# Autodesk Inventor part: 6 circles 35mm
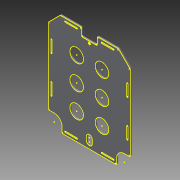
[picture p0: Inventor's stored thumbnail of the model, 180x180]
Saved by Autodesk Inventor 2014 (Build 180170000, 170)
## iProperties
Created: 2014-05
Part Number: 6 circles 35mm
Material: Generic
Document SubType Name: Modeling
Designer: Designer
Density: 1 g/cm^3
Appearance: Default
Author: Designer
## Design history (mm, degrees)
sketch "Sketch1" dims "d120" = 10, "d132" = 10
  geometry: L1 (97.5, 0)-(97.5, 10); L2 (82.5, 10)-(82.5, 0); L3 (17, 40)-(25, 40); L4 (25, 20)-(17, 20); L5 (15, 22)-(15, 38); L6 (195, 214.172)-(195, 22); L7 (158, -15)-(22, -15); L8 (-15, 22)-(-15, 214.172); L9 (-13, 20)-(0, 20); L10 (20, 0)-(20, -13); L11 (160, -13)-(160, 0); L12 (180, 20)-(193, 20); L13 (70, 243)-(70, 227); L14 (72, 225)-(108, 225); L15 (110, 227)-(110, 243); L16 (15, 245)-(-14.414, 215.586); L17 (165.586, 244.414)-(194.414, 215.586); L18 (15, 245)-(68, 245); L19 (112, 245)-(164.172, 245); L20 (27, 38)-(27, 22); C1 r 3 at (90, 220); C2 r 12.5 at (57.5, 177.5); C3 r 12.5 at (122.5, 177.5); C4 r 12.5 at (57.5, 115); C5 r 12.5 at (122.5, 115); C6 r 12.5 at (57.5, 52.5); C7 r 12.5 at (122.5, 52.5); A1 r 7.5 centre (90, 10) between (97.5, 10) and (82.5, 10); A2 r 20 centre (0, 0) between (20, 0) and (0, 20); A3 r 20 centre (180, 0) between (180, 20) and (160, 0); A4 r 7.5 centre (90, 0) between (82.5, 0) and (97.5, 0); A5 r 2 centre (17, 38) between (17, 40) and (15, 38); A6 r 2 centre (25, 22) between (25, 20) and (27, 22); A7 r 2 centre (17, 22) between (15, 22) and (17, 20); A8 r 2 centre (25, 38) between (27, 38) and (25, 40); A9 r 2 centre (68, 243) between (70, 243) and (68, 245); A10 r 2 centre (-13, 214.172) between (-14.414, 215.586) and (-15, 214.172); A11 r 2 centre (72, 227) between (70, 227) and (72, 225); A12 r 2 centre (108, 227) between (108, 225) and (110, 227); A13 r 2 centre (112, 243) between (112, 245) and (110, 243); A14 r 2 centre (164.172, 243) between (165.586, 244.414) and (164.172, 245); A15 r 2 centre (193, 214.172) between (195, 214.172) and (194.414, 215.586); A16 r 2 centre (193, 22) between (193, 20) and (195, 22); A17 r 2 centre (158, -13) between (158, -15) and (160, -13); A18 r 2 centre (22, -13) between (20, -13) and (22, -15); A19 r 2 centre (-13, 22) between (-15, 22) and (-13, 20); 19 further points
  constraints: 40 end point, 38 point on circle, 34 point on line, 34 tangent, 26 centre point, 11 equal radius, 11 perpendicular, 6 parallel, 4 horizontal, 1 vertical, 10 other
  dimensions: "d55" = 260 distance between parallel lines of L7 L19; "d56" = 210 distance between parallel lines of L6 L8; "d107" = 20 distance from line of C1.centre L13; "d111" = 5 distance from line of L14 C1.centre; "d112" = 42.5 vertical distance of C1.centre C2.centre; "d113" = 32.5 horizontal distance of C2.centre C1.centre; "d114" = 25 diameter of C2; "d117" = 65 distance of C2.centre C3.centre; "d125" = 72.5 distance from line of L6 C3.centre; "d126" = 72.5 distance from line of L8 C2.centre (derived); "d129" = 62.5 distance of C2.centre C4.centre; "d134" = 12.5 distance from line of C3.centre L15
extrude "Extrusion1" new body sketch "Sketch1" distance "d69" = 4; taper "d70" = 0 deg
sketch "Sketch2"
  geometry: L1 (30, 24)-(30, 104) reference; L2 (-15, 214.172)-(-15, 22) reference; L3 (68, 245)-(15, 245) reference; L4 (-7.5, 180)-(-7.5, 150); L5 (-9, 180)-(-9, 150); L6 (-6, 150)-(-6, 180); A1 r 1.5 centre (-7.5, 180) between (-6, 180) and (-9, 180); A2 r 1.5 centre (-7.5, 150) between (-9, 150) and (-6, 150); 1 further point
  constraints: 8 end point, 4 point on circle, 4 tangent, 2 centre point, 2 parallel, 1 midpoint
  dimensions: "d72" = 30 distance of L6.start L6.end; "d73" = 3 distance between parallel lines of L6 L5; "d74" = 65 distance from line of L4.start L3; "d75" = 6 distance between parallel lines of L5 L2
extrude "Extrusion2" cut sketch "Sketch2" distance "d76" = 4; taper "d77" = 0 deg
sketch "Sketch3"
  geometry: L1 (82, 22)-(32, 22) reference; L2 (70, 227)-(70, 243) reference; L3 (68, 245)-(15, 245) reference; L4 (28, 237.5)-(58, 237.5); L5 (28, 239)-(58, 239); L6 (58, 236)-(28, 236); A1 r 1.5 centre (28, 237.5) between (28, 239) and (28, 236); A2 r 1.5 centre (58, 237.5) between (58, 236) and (58, 239); 1 further point
  constraints: 8 end point, 4 point on circle, 4 tangent, 2 centre point, 2 parallel, 1 midpoint
  dimensions: "d84" = 3 distance between parallel lines of L5 L6; "d85" = 30 distance of L5.start L5.end; "d86" = 6 distance between parallel lines of L3 L5; "d87" = 12 distance from line of L2 L4.end
extrude "Extrusion3" cut sketch "Sketch3" distance "d88" = 4; taper "d89" = 0 deg
pattern_linear "Rectangular Pattern2" dims "d92" = 94, "d95" = 245
pattern_linear "Rectangular Pattern3" dims "d137" = 195, "d140" = 95
sketch "Sketch6" dims "d161" = 10, "d162" = 10
  geometry: L1 (97.5, 0)-(97.5, 10); L2 (82.5, 10)-(82.5, 0); L3 (17, 40)-(25, 40); L4 (25, 20)-(17, 20); L5 (15, 22)-(15, 38); L6 (195, 214.172)-(195, 22); L7 (158, -15)-(22, -15); L8 (-15, 22)-(-15, 214.172); L9 (-13, 20)-(0, 20); L10 (20, 0)-(20, -13); L11 (160, -13)-(160, 0); L12 (180, 20)-(193, 20); L13 (70, 243)-(70, 227); L14 (72, 225)-(108, 225); L15 (110, 227)-(110, 243); L16 (15, 245)-(-14.414, 215.586); L17 (165.586, 244.414)-(194.414, 215.586); L18 (15, 245)-(68, 245); L19 (112, 245)-(164.172, 245); L20 (27, 38)-(27, 22); C1 r 3 at (90, 220); C2 r 17.5 at (57.5, 177.5); C3 r 17.5 at (122.5, 177.5); C4 r 17.5 at (57.5, 115); C5 r 17.5 at (122.5, 115); C6 r 17.5 at (57.5, 52.5); C7 r 17.5 at (122.5, 52.5); A1 r 7.5 centre (90, 10) between (97.5, 10) and (82.5, 10); A2 r 20 centre (0, 0) between (20, 0) and (0, 20); A3 r 20 centre (180, 0) between (180, 20) and (160, 0); A4 r 7.5 centre (90, 0) between (82.5, 0) and (97.5, 0); A5 r 2 centre (17, 38) between (17, 40) and (15, 38); A6 r 2 centre (25, 22) between (25, 20) and (27, 22); A7 r 2 centre (17, 22) between (15, 22) and (17, 20); A8 r 2 centre (25, 38) between (27, 38) and (25, 40); A9 r 2 centre (68, 243) between (70, 243) and (68, 245); A10 r 2 centre (-13, 214.172) between (-14.414, 215.586) and (-15, 214.172); A11 r 2 centre (72, 227) between (70, 227) and (72, 225); A12 r 2 centre (108, 227) between (108, 225) and (110, 227); A13 r 2 centre (112, 243) between (112, 245) and (110, 243); A14 r 2 centre (164.172, 243) between (165.586, 244.414) and (164.172, 245); A15 r 2 centre (193, 214.172) between (195, 214.172) and (194.414, 215.586); A16 r 2 centre (193, 22) between (193, 20) and (195, 22); A17 r 2 centre (158, -13) between (158, -15) and (160, -13); A18 r 2 centre (22, -13) between (20, -13) and (22, -15); A19 r 2 centre (-13, 22) between (-15, 22) and (-13, 20); 19 further points
  constraints: 40 end point, 38 point on circle, 34 point on line, 34 tangent, 26 centre point, 11 equal radius, 11 perpendicular, 6 parallel, 4 horizontal, 1 vertical, 10 other
  dimensions: "d149" = 260 distance between parallel lines of L7 L19; "d150" = 210 distance between parallel lines of L6 L8; "d151" = 20 distance from line of C1.centre L13; "d152" = 5 distance from line of L14 C1.centre; "d153" = 42.5 vertical distance of C1.centre C2.centre; "d154" = 32.5 horizontal distance of C2.centre C1.centre; "d155" = 35 diameter of C2; "d156" = 65 distance of C2.centre C3.centre; "d157" = 72.5 distance from line of L6 C3.centre; "d158" = 72.5 distance from line of L8 C2.centre (derived); "d159" = 62.5 distance of C2.centre C4.centre; "d160" = 12.5 distance from line of C3.centre L15
extrude "Extrusion4" cut sketch "Sketch6" distance "d163" = 10; taper "d164" = 0 deg
sketch "Sketch7"
  geometry: L1 (186, 55)-(186, 85) reference; L2 (189, 85)-(189, 55) reference; L3 (-9, 55)-(-9, 85) reference; L4 (-6, 85)-(-6, 55) reference; L5 (186, 150)-(186, 180) reference; L6 (189, 180)-(189, 150) reference; L7 (122, -6)-(152, -6) reference; L8 (152, -9)-(122, -9) reference; L9 (28, -6)-(58, -6) reference; L10 (58, -9)-(28, -9) reference; L11 (122, 239)-(152, 239) reference; L12 (152, 236)-(122, 236) reference; L13 (28, 239)-(58, 239) reference; L14 (58, 236)-(28, 236) reference; L15 (-9, 150)-(-9, 180) reference; L16 (-6, 180)-(-6, 150) reference; L17 (82.5, 0)-(82.5, 10) reference; L18 (97.5, 10)-(97.5, 0) reference; L19 (15, 245)-(-14.414, 215.586) reference; L20 (-15, 214.172)-(-15, 22) reference; L21 (-13, 20)-(0, 20) reference; L22 (20, 0)-(20, -13) reference; L23 (22, -15)-(158, -15) reference; L24 (160, -13)-(160, 0) reference; L25 (180, 20)-(193, 20) reference; L26 (195, 22)-(195, 214.172) reference; L27 (194.414, 215.586)-(165.586, 244.414) reference; L28 (164.172, 245)-(112, 245) reference; L29 (110, 243)-(110, 227) reference; L30 (108, 225)-(72, 225) reference; L31 (70, 227)-(70, 243) reference; L32 (68, 245)-(15, 245) reference; C1 r 17.5 at (57.5, 52.5) reference; C2 r 17.5 at (57.5, 115) reference; C3 r 17.5 at (57.5, 177.5) reference; C4 r 17.5 at (122.5, 177.5) reference; C5 r 17.5 at (122.5, 115) reference; C6 r 17.5 at (122.5, 52.5) reference; C7 r 3 at (90, 220) reference; A1 r 1.5 centre (187.5, 55) between (186, 55) and (189, 55) reference; A2 r 1.5 centre (187.5, 85) between (189, 85) and (186, 85) reference; A3 r 1.5 centre (-7.5, 55) between (-9, 55) and (-6, 55) reference; A4 r 1.5 centre (-7.5, 85) between (-6, 85) and (-9, 85) reference; A5 r 1.5 centre (187.5, 150) between (186, 150) and (189, 150) reference; A6 r 1.5 centre (187.5, 180) between (189, 180) and (186, 180) reference; A7 r 1.5 centre (122, -7.5) between (122, -6) and (122, -9) reference; A8 r 1.5 centre (152, -7.5) between (152, -9) and (152, -6) reference; A9 r 1.5 centre (28, -7.5) between (28, -6) and (28, -9) reference; A10 r 1.5 centre (58, -7.5) between (58, -9) and (58, -6) reference; A11 r 1.5 centre (122, 237.5) between (122, 239) and (122, 236) reference; A12 r 1.5 centre (152, 237.5) between (152, 236) and (152, 239) reference; A13 r 1.5 centre (28, 237.5) between (28, 239) and (28, 236) reference; A14 r 1.5 centre (58, 237.5) between (58, 236) and (58, 239) reference; A15 r 1.5 centre (-7.5, 150) between (-9, 150) and (-6, 150) reference; A16 r 1.5 centre (-7.5, 180) between (-6, 180) and (-9, 180) reference; A17 r 7.5 centre (90, 10) between (97.5, 10) and (82.5, 10) reference; A18 r 7.5 centre (90, 0) between (82.5, 0) and (97.5, 0) reference; A19 r 2 centre (-13, 214.172) between (-14.414, 215.586) and (-15, 214.172) reference; A20 r 2 centre (-13, 22) between (-15, 22) and (-13, 20) reference; A21 r 20 centre (0, 0) between (20, 0) and (0, 20) reference; A22 r 2 centre (22, -13) between (20, -13) and (22, -15) reference; A23 r 2 centre (158, -13) between (158, -15) and (160, -13) reference; A24 r 20 centre (180, 0) between (180, 20) and (160, 0) reference; A25 r 2 centre (193, 22) between (193, 20) and (195, 22) reference; A26 r 2 centre (193, 214.172) between (195, 214.172) and (194.414, 215.586) reference; A27 r 2 centre (164.172, 243) between (165.586, 244.414) and (164.172, 245) reference; A28 r 2 centre (112, 243) between (112, 245) and (110, 243) reference; A29 r 2 centre (108, 227) between (108, 225) and (110, 227) reference; A30 r 2 centre (72, 227) between (70, 227) and (72, 225) reference; A31 r 2 centre (68, 243) between (70, 243) and (68, 245) reference
body "Solid1"
feature "耀䀸"
